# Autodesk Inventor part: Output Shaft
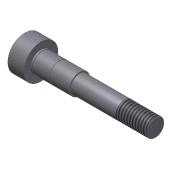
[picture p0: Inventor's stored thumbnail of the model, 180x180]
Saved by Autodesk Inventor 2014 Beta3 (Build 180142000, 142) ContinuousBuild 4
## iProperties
Created: 2011-01
Part Number: Output Shaft
Material: Steel
Document SubType Name: Modeling
Designer: Beta-8540w
Density: 1 g/cm^3
Appearance: Steel
CustomPartVersion: 1
Author: Beta-8540w
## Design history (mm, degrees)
sketch "Main Sketch"
  geometry: L1 (0, 0)-(95, 0) reference; L2 (0, 0)-(0, 12.5); L3 (12, 12.5)-(12, 7.5); L4 (0, 12.5)-(12, 12.5); L5 (40, 7.5)-(40, 6.5); L6 (12, 7.5)-(40, 7.5); L7 (95, 6.5)-(95, 0); L8 (40, 6.5)-(95, 6.5)
  constraints: 16 end point, 5 horizontal, 4 vertical
  dimensions: "d3" = 25 diameter of L4 L1 (derived); "d4" = 15 diameter of L6 L1 (derived); "d5" = 13 diameter of L8 L1 (derived)
revolve "Revolution1" sketch "Main Sketch" stored, may be unused: angle "d6" = 0 deg
node "Retaining Ring Groove1"
node "Retaining Ring Groove2"
chamfer "Chamfer2" distance "d10" = 0.5; stored, may be unused: second distance "d11" = 0.125, angle "d12" = 45 deg
thread "Thread1" dims "d13" = 22, "d14" = 0
node "Spur Gear Teeth1"
body "Solid1"
feature "iFeature27:1"
feature "iFeature27:2"
feature "Cut Gear"
other parameters: "d0" = 0, "d1" = 0, "d2" = 0
